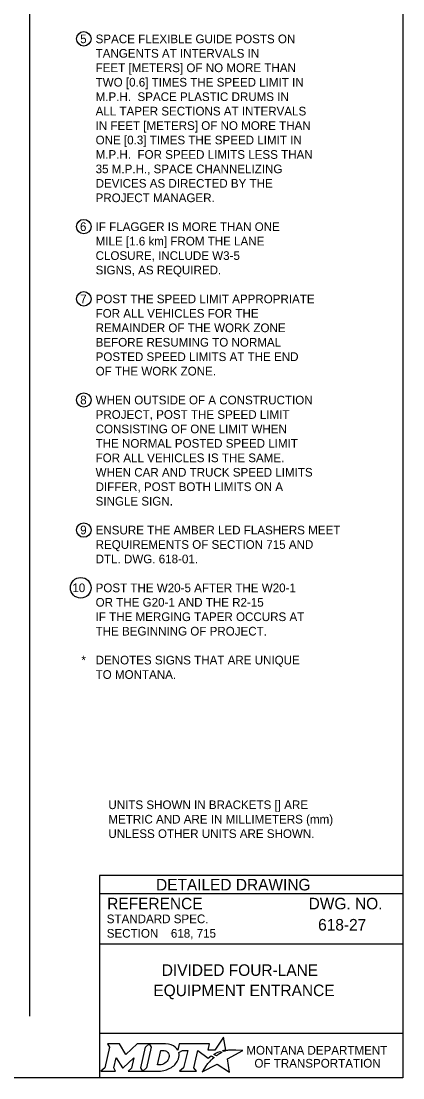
# Model space of a CAD drawing. Extents: x 49991.4 to 50021, y 49987.6 to 50011.4.
# Drawn here: x 50014.11 to 50016.75, y 49987.8 to 49995.11 of the extents above; entities that cross this region are included whole.
import ezdxf

# ---------------------------------------------------------------- set-up
doc = ezdxf.new("R2010")
doc.units = 0
for name, color, linetype in [('Default', 7, 'Continuous'), ('Level 1', 7, 'Continuous'), ('Level 2', 7, 'Continuous'), ('Level 3', 7, 'Continuous'), ('Level 5', 7, 'Continuous')]:
    doc.layers.add(name, color=color, linetype=linetype)

msp = doc.modelspace()

# ---------------------------------------------------------------- linework, layer by layer
at = {"layer": 'Default'}
for points in [[(50015.5126, 49987.9811), (50015.5023, 49987.9867), (50015.5139, 49987.9895), (50015.5255, 49987.9915), (50015.5081, 49988.0816), (50015.4486, 49987.9903), (50015.4013, 49987.9896), (50015.4116, 49988.0337), (50015.2024, 49988.0338), (50015.1923, 49987.9913), (50015.1865, 49987.9996)], [(50014.7056, 49988.0338), (50014.7197, 49988.0104), (50014.6862, 49987.8671), (50014.6605, 49987.8446), (50014.7621, 49987.8446), (50014.7486, 49987.8674), (50014.7648, 49987.9375), (50014.8085, 49987.8685), (50014.8138, 49987.8685), (50014.8889, 49987.938), (50014.8725, 49987.8669), (50014.8478, 49987.8449), (50014.9494, 49987.8449), (50014.9356, 49987.8682), (50014.9688, 49988.0106)], [(50014.9688, 49988.0106), (50014.9941, 49988.0338), (50014.9117, 49988.0338), (50014.8321, 49987.9608), (50014.7876, 49988.0335), (50014.7056, 49988.0338)], [(50015.1077, 49988.0338), (50014.9941, 49988.0338), (50015.0088, 49988.0109), (50014.9749, 49987.8671), (50014.9494, 49987.8449), (50015.06, 49987.8449)], [(50015.1317, 49987.9471), (50015.1305, 49987.939), (50015.1273, 49987.9297), (50015.1231, 49987.9215), (50015.1175, 49987.914), (50015.111, 49987.9071), (50015.1031, 49987.9008), (50015.0948, 49987.8961), (50015.0857, 49987.8922), (50015.0766, 49987.8899), (50015.0674, 49987.889), (50015.0515, 49987.889), (50015.0751, 49987.989), (50015.0911, 49987.989), (50015.0987, 49987.9884), (50015.1063, 49987.9865), (50015.1129, 49987.9835), (50015.119, 49987.9793), (50015.1238, 49987.9743), (50015.1275, 49987.9683), (50015.1302, 49987.9621), (50015.1318, 49987.9547), (50015.1318, 49987.9517), (50015.1317, 49987.9471)], [(50015.1991, 49987.9747), (50015.2237, 49987.9878), (50015.2606, 49987.9878), (50015.232, 49987.8673), (50015.2045, 49987.8446), (50015.3207, 49987.8446), (50015.3037, 49987.8675), (50015.3319, 49987.9877), (50015.4032, 49987.936), (50015.4243, 49987.9511), (50015.444, 49987.9402)], [(50015.3882, 49987.8843), (50015.3729, 49987.8599), (50015.3682, 49987.8524), (50015.3624, 49987.8438), (50015.3601, 49987.8395), (50015.4654, 49987.8926), (50015.5493, 49987.8375), (50015.5362, 49987.9302), (50015.6431, 49987.9886), (50015.5938, 49987.9894), (50015.5637, 49987.9898), (50015.5429, 49987.9901), (50015.5361, 49987.9886), (50015.5312, 49987.9874), (50015.5228, 49987.9851), (50015.5126, 49987.9811)], [(50015.4622, 49987.9535), (50015.4598, 49987.9518), (50015.4415, 49987.9614), (50015.4518, 49987.9671), (50015.4559, 49987.9693), (50015.4645, 49987.9733), (50015.4702, 49987.9759), (50015.4781, 49987.9789), (50015.4854, 49987.9816), (50015.4972, 49987.9742), (50015.4932, 49987.9721), (50015.4886, 49987.9696), (50015.4844, 49987.9674), (50015.4794, 49987.9645), (50015.4775, 49987.9634), (50015.4748, 49987.9618), (50015.4723, 49987.9604), (50015.47, 49987.9588), (50015.4674, 49987.957), (50015.4647, 49987.9552), (50015.4622, 49987.9535)], [(50015.1057, 49987.8522), (50015.1141, 49987.8548), (50015.1271, 49987.8602), (50015.1475, 49987.8712)], [(50015.4021, 49987.9004), (50015.4021, 49987.9004)]]:
    msp.add_lwpolyline(points, dxfattribs=at)
for centre, radius, start, end in [((50015.0868, 49987.9727), 0.1183, 300.91025, 339.13831), ((50015.1308, 49987.9554), 0.0709, 339.53292, 15.85821)]:
    msp.add_arc(centre, radius, start, end, dxfattribs=at)
for centre, major_axis, ratio, start_param, end_param in [((50015.1056, 49987.9864), (0.0834, -0.0037), 0.568097, 0.61298, 1.570796), ((50015.1612, 49987.9937), (0.0361, -0.0295), 0.469099, 1.225588, 1.570796), ((50015.4119, 49987.9106), (-0.0098, -0.0102), 0.016458, 3.141593, 6.279097), ((50015.4329, 49987.9305), (-0.0112, -0.0097), 0.021651, 3.157348, 6.283185), ((50015.0603, 49987.9932), (0, 0.1484), 0.987302, 3.139398, 3.456847), ((50015.3952, 49987.8923), (-0.00694, -0.00806), 0.008222, 0, 3.137361)]:
    msp.add_ellipse(centre, major_axis=major_axis, ratio=ratio, start_param=start_param, end_param=end_param, dxfattribs=at)
at = {"layer": 'Level 1'}
msp.add_lwpolyline([(49999.3835, 49998.9992), (50016.7501, 49998.9992), (50016.7501, 49987.7988), (49999.3835, 49987.7988)], close=True, dxfattribs=at)
at = {"layer": 'Level 2'}
for centre, radius in [((50014.5416, 49994.9912), 0.05), ((50014.5416, 49993.6912), 0.05), ((50014.5416, 49993.1912), 0.05), ((50014.5416, 49992.4912), 0.05), ((50014.5416, 49991.5912), 0.05), ((50014.5202, 49991.1912), 0.0714)]:
    msp.add_circle(centre, radius, dxfattribs=at)
at = {"layer": 'Level 3'}
msp.add_line((50014.1659, 49998.9992), (50014.1659, 49988.2257), dxfattribs=at)
at = {"layer": 'Level 5'}
for p, q in [((50016.7501, 49989.1988), (50014.6501, 49989.1988)), ((50014.6501, 49989.1988), (50014.6501, 49987.7988)), ((50016.7501, 49989.0738), (50014.6501, 49989.0738)), ((50015.1444, 49988.7993), (50015.1444, 49988.7993)), ((50016.3862, 49988.8587), (50016.3862, 49988.8587)), ((50016.7501, 49988.7238), (50014.6501, 49988.7238)), ((50015.7001, 49988.4747), (50015.7001, 49988.4747)), ((50016.7501, 49988.1057), (50014.6501, 49988.1057))]:
    msp.add_line(p, q, dxfattribs=at)

# ---------------------------------------------------------------- texts
at = {"layer": 'Default'}
for s, p in [('MONTANA DEPARTMENT', (50015.6663, 49987.96)), ('OF TRANSPORTATION', (50015.7225, 49987.87))]:
    msp.add_text(s, height=0.06, dxfattribs=at).set_placement(p)
at = {"layer": 'Level 2'}
for s, height, p in [('5', 0.06, (50014.5167, 49994.9612)), ('SPACE FLEXIBLE GUIDE POSTS ON', 0.06, (50014.6234, 49994.9608)), ('TANGENTS AT INTERVALS IN', 0.06, (50014.6234, 49994.8608)), ('FEET [METERS] OF NO MORE THAN', 0.06, (50014.6234, 49994.7608)), ('TWO [0.6] TIMES THE SPEED LIMIT IN', 0.06, (50014.6234, 49994.6608)), ('M.P.H.  SPACE PLASTIC DRUMS IN', 0.06, (50014.6234, 49994.5608)), ('ALL TAPER SECTIONS AT INTERVALS', 0.06, (50014.6234, 49994.4608)), ('IN FEET [METERS] OF NO MORE THAN', 0.06, (50014.6234, 49994.3608)), ('ONE [0.3] TIMES THE SPEED LIMIT IN', 0.06, (50014.6234, 49994.2608)), ('M.P.H.  FOR SPEED LIMITS LESS THAN', 0.06, (50014.6234, 49994.1608)), ('35 M.P.H., SPACE CHANNELIZING', 0.06, (50014.6234, 49994.0608)), ('DEVICES AS DIRECTED BY THE', 0.06, (50014.6234, 49993.9608)), ('PROJECT MANAGER.', 0.06, (50014.6234, 49993.8608)), ('6', 0.06, (50014.5151, 49993.6612)), ('IF FLAGGER IS MORE THAN ONE', 0.06, (50014.6234, 49993.6608)), ('MILE [1.6 km] FROM THE LANE', 0.06, (50014.6234, 49993.5608)), ('CLOSURE, INCLUDE W3-5', 0.06, (50014.6234, 49993.4608)), ('SIGNS, AS REQUIRED.', 0.06, (50014.6234, 49993.3608)), ('7', 0.06, (50014.5167, 49993.1612)), ('POST THE SPEED LIMIT APPROPRIATE ', 0.06, (50014.6234, 49993.1608)), ('FOR ALL VEHICLES FOR THE', 0.06, (50014.6234, 49993.0608)), ('REMAINDER OF THE WORK ZONE', 0.06, (50014.6234, 49992.9608)), ('BEFORE RESUMING TO NORMAL', 0.06, (50014.6234, 49992.8608)), ('POSTED SPEED LIMITS AT THE END', 0.06, (50014.6234, 49992.7608)), ('OF THE WORK ZONE.', 0.06, (50014.6234, 49992.6608)), ('8', 0.06, (50014.5167, 49992.4612)), ('WHEN OUTSIDE OF A CONSTRUCTION', 0.06, (50014.6234, 49992.4608)), ('PROJECT, POST THE SPEED LIMIT', 0.06, (50014.6234, 49992.3608)), ('CONSISTING OF ONE LIMIT WHEN', 0.06, (50014.6234, 49992.2608)), ('THE NORMAL POSTED SPEED LIMIT', 0.06, (50014.6234, 49992.1608)), ('FOR ALL VEHICLES IS THE SAME.  ', 0.06, (50014.6234, 49992.0608)), ('WHEN CAR AND TRUCK SPEED LIMITS', 0.06, (50014.6234, 49991.9608)), ('DIFFER, POST BOTH LIMITS ON A', 0.06, (50014.6234, 49991.8608)), ('SINGLE SIGN.', 0.06, (50014.6234, 49991.7608)), ('9', 0.06, (50014.5165, 49991.5612)), ('ENSURE THE AMBER LED FLASHERS MEET ', 0.06, (50014.6234, 49991.5608)), ('REQUIREMENTS OF SECTION 715 AND', 0.06, (50014.6234, 49991.4608)), ('DTL. DWG. 618-01.', 0.06, (50014.6234, 49991.3608)), ('10', 0.06, (50014.4622, 49991.1612)), ('POST THE W20-5 AFTER THE W20-1', 0.06, (50014.6234, 49991.1608)), ('OR THE G20-1 AND THE R2-15', 0.06, (50014.6234, 49991.0608)), ('IF THE MERGING TAPER OCCURS AT', 0.06, (50014.6234, 49990.9608)), ('THE BEGINNING OF PROJECT.', 0.06, (50014.6234, 49990.8608)), ('*', 0.06, (50014.5249, 49990.6608)), ('DENOTES SIGNS THAT ARE UNIQUE', 0.06, (50014.6234, 49990.6608)), ('TO MONTANA.', 0.06, (50014.6234, 49990.5608)), ('UNITS SHOWN IN BRACKETS [] ARE ', 0.06, (50014.7117, 49989.6593)), ('METRIC AND ARE IN MILLIMETERS (mm) ', 0.06, (50014.7117, 49989.5593)), ('UNLESS OTHER UNITS ARE SHOWN.', 0.06, (50014.7117, 49989.4593)), ('618-27', 0.08, (50016.1635, 49988.8187)), ('618, 715', 0.06, (50015.1443, 49988.7693)), ('DIVIDED FOUR-LANE', 0.08, (50015.0814, 49988.5047)), ('EQUIPMENT ENTRANCE', 0.08, (50015.0231, 49988.3647))]:
    msp.add_text(s, height=height, dxfattribs=at).set_placement(p)
at = {"layer": 'Level 5'}
for s, height, p in [('DETAILED DRAWING', 0.0799, (50015.0418, 49989.0963)), ('REFERENCE', 0.08, (50014.7037, 49988.9654)), ('DWG. NO.', 0.08, (50016.0979, 49988.9654)), ('STANDARD SPEC.', 0.06, (50014.7004, 49988.8694)), ('SECTION', 0.06, (50014.7004, 49988.7694))]:
    msp.add_text(s, height=height, dxfattribs=at).set_placement(p)

doc.saveas('drawing.dxf')
